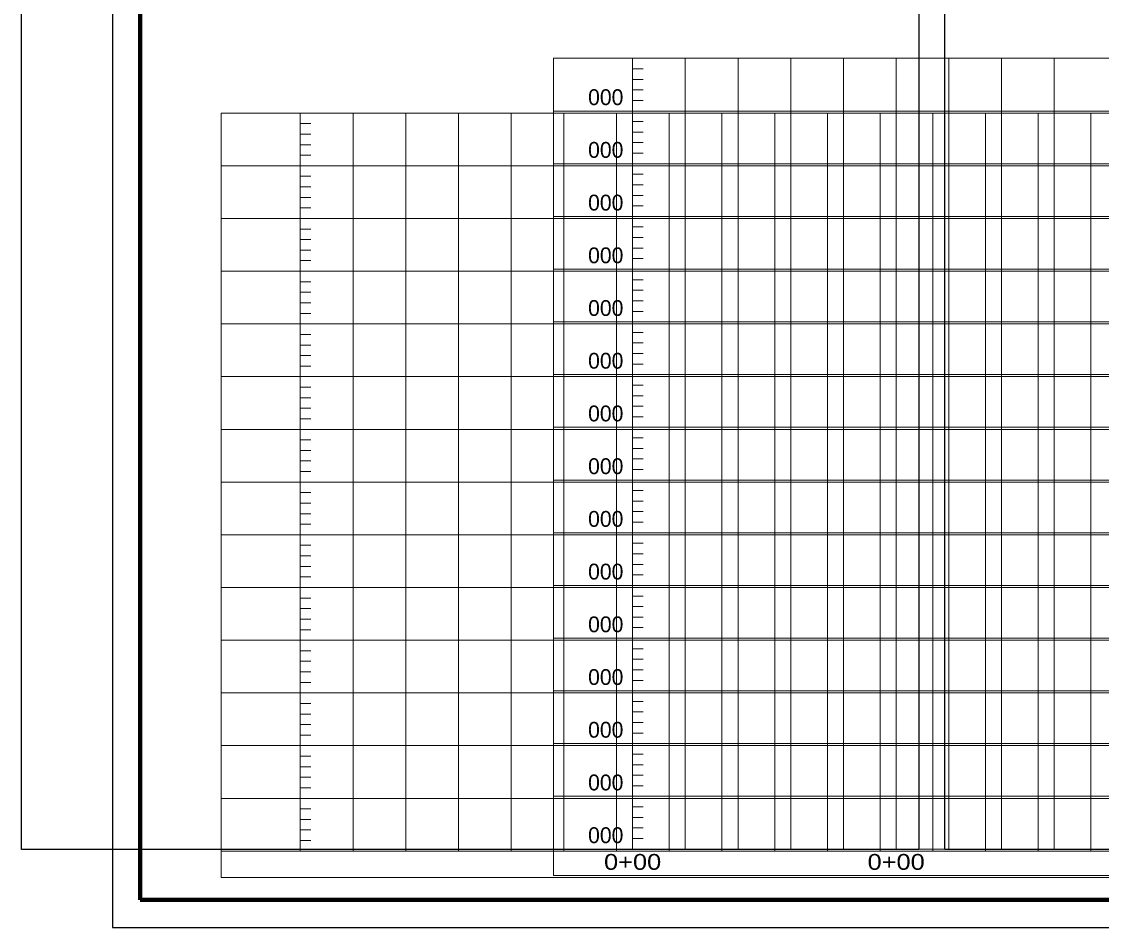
# Model space of a CAD drawing. Extents: x 2246932 to 2264252, y 7095151 to 7098651.
# Drawn here: x 2246932 to 2248981, y 7095151 to 7096869 of the extents above; entities that cross this region are included whole.
import ezdxf
from ezdxf.enums import TextEntityAlignment as Align

# ---------------------------------------------------------------- set-up
doc = ezdxf.new("R2010")
doc.units = 0
doc.header["$LTSCALE"] = 12
for name, color, linetype, lineweight in [('1', 7, 'Continuous', 80), ('59', 7, 'Continuous', 13), ('62', 7, 'Continuous', 13), ('63', 7, 'Continuous', 25)]:
    doc.layers.add(name, color=color, linetype=linetype, lineweight=lineweight)
doc.layers.add('22', color=7, linetype='Continuous')

msp = doc.modelspace()

# ---------------------------------------------------------------- linework, layer by layer
at = {"layer": '1'}
for p, q in [((2247157.08, 7098598.35), (2247157.09, 7095203.35)), ((2247157.09, 7095203.35), (2264052.09, 7095203.35))]:
    msp.add_line(p, q, dxfattribs=at)
at = {"layer": '1', "lineweight": 25}
msp.add_line((2247104.59, 7095150.85), (2264104.59, 7095150.85), dxfattribs=at)
msp.add_lwpolyline([(2264104.59, 7095150.85), (2264104.59, 7098650.85), (2247104.59, 7098650.85), (2247104.59, 7095150.85)], dxfattribs=at)
at = {"layer": '59'}
for p, q in [((2247310.97, 7096695.64), (2262610.97, 7096695.64)), ((2247310.97, 7096695.64), (2247310.97, 7095995.64)), ((2247460.97, 7095995.64), (2247460.97, 7096695.64)), ((2247560.97, 7096695.64), (2247560.97, 7095995.64)), ((2247660.97, 7095295.64), (2247660.97, 7096695.64)), ((2247760.97, 7095295.64), (2247760.97, 7096695.64)), ((2247860.97, 7095295.64), (2247860.97, 7096695.64)), ((2247960.97, 7096695.64), (2247960.97, 7095295.64)), ((2248060.97, 7095295.64), (2248060.97, 7096695.64)), ((2248160.97, 7095295.64), (2248160.97, 7096695.64)), ((2248260.97, 7095295.64), (2248260.97, 7096695.64)), ((2248360.97, 7095295.64), (2248360.97, 7096695.64)), ((2248460.97, 7096695.64), (2248460.97, 7095295.64)), ((2248560.97, 7095295.64), (2248560.97, 7096695.64)), ((2248660.97, 7095295.64), (2248660.97, 7096695.64)), ((2248760.97, 7095295.64), (2248760.97, 7096695.64)), ((2248860.97, 7095295.64), (2248860.97, 7096695.64)), ((2248960.97, 7096695.64), (2248960.97, 7095295.64)), ((2247460.97, 7096675.64), (2247480.97, 7096675.64)), ((2247460.97, 7096655.64), (2247480.97, 7096655.64)), ((2247460.97, 7096635.64), (2247480.97, 7096635.64)), ((2247460.97, 7096615.64), (2247480.97, 7096615.64)), ((2247310.97, 7096595.64), (2247460.97, 7096595.64)), ((2247460.97, 7096575.64), (2247480.97, 7096575.64)), ((2247460.97, 7096555.64), (2247480.97, 7096555.64)), ((2247460.97, 7096535.64), (2247480.97, 7096535.64)), ((2247460.97, 7096515.64), (2247480.97, 7096515.64)), ((2247310.97, 7096495.64), (2247460.97, 7096495.64)), ((2247460.97, 7096475.64), (2247480.97, 7096475.64)), ((2247460.97, 7096455.64), (2247480.97, 7096455.64)), ((2247460.97, 7096435.64), (2247480.97, 7096435.64)), ((2247460.97, 7096415.64), (2247480.97, 7096415.64)), ((2247310.97, 7096395.64), (2247460.97, 7096395.64)), ((2247460.97, 7096375.64), (2247480.97, 7096375.64)), ((2247460.97, 7096355.64), (2247480.97, 7096355.64)), ((2247460.97, 7096335.64), (2247480.97, 7096335.64)), ((2247460.97, 7096315.64), (2247480.97, 7096315.64)), ((2247310.97, 7096295.64), (2247460.97, 7096295.64)), ((2247460.97, 7096275.64), (2247480.97, 7096275.64)), ((2247460.97, 7096255.64), (2247480.97, 7096255.64)), ((2247460.97, 7096235.64), (2247480.97, 7096235.64)), ((2247460.97, 7096215.64), (2247480.97, 7096215.64)), ((2247310.97, 7096195.64), (2247460.97, 7096195.64)), ((2247460.97, 7096175.64), (2247480.97, 7096175.64)), ((2247460.97, 7096155.64), (2247480.97, 7096155.64)), ((2247460.97, 7096135.64), (2247480.97, 7096135.64)), ((2247460.97, 7096115.64), (2247480.97, 7096115.64)), ((2247310.97, 7096095.64), (2247460.97, 7096095.64)), ((2247460.97, 7096075.64), (2247480.97, 7096075.64)), ((2247460.97, 7096055.64), (2247480.97, 7096055.64)), ((2247460.97, 7096035.64), (2247480.97, 7096035.64)), ((2247460.97, 7096015.64), (2247480.97, 7096015.64)), ((2247310.97, 7095995.64), (2247310.97, 7095245.64)), ((2247310.97, 7095995.64), (2247460.97, 7095995.64)), ((2247460.97, 7095295.64), (2247460.97, 7095995.64)), ((2247560.97, 7095995.64), (2247560.97, 7095295.64)), ((2247460.97, 7095975.64), (2247480.97, 7095975.64)), ((2247460.97, 7095955.64), (2247480.97, 7095955.64)), ((2247460.97, 7095935.64), (2247480.97, 7095935.64)), ((2247460.97, 7095915.64), (2247480.97, 7095915.64)), ((2247310.97, 7095895.64), (2247460.97, 7095895.64)), ((2247460.97, 7095875.64), (2247480.97, 7095875.64)), ((2247460.97, 7095855.64), (2247480.97, 7095855.64)), ((2247460.97, 7095835.64), (2247480.97, 7095835.64)), ((2247460.97, 7095815.64), (2247480.97, 7095815.64)), ((2247310.97, 7095795.64), (2247460.97, 7095795.64)), ((2247460.97, 7095775.64), (2247480.97, 7095775.64)), ((2247460.97, 7095755.64), (2247480.97, 7095755.64)), ((2247460.97, 7095735.64), (2247480.97, 7095735.64)), ((2247460.97, 7095715.64), (2247480.97, 7095715.64)), ((2247310.97, 7095695.64), (2247460.97, 7095695.64)), ((2247460.97, 7095675.64), (2247480.97, 7095675.64)), ((2247460.97, 7095655.64), (2247480.97, 7095655.64)), ((2247460.97, 7095635.64), (2247480.97, 7095635.64)), ((2247460.97, 7095615.64), (2247480.97, 7095615.64)), ((2247310.97, 7095595.64), (2247460.97, 7095595.64)), ((2247460.97, 7095575.64), (2247480.97, 7095575.64)), ((2247460.97, 7095555.64), (2247480.97, 7095555.64)), ((2247460.97, 7095535.64), (2247480.97, 7095535.64)), ((2247460.97, 7095515.64), (2247480.97, 7095515.64)), ((2247310.97, 7095495.64), (2247460.97, 7095495.64)), ((2247460.97, 7095475.64), (2247480.97, 7095475.64)), ((2247460.97, 7095455.64), (2247480.97, 7095455.64)), ((2247460.97, 7095435.64), (2247480.97, 7095435.64)), ((2247460.97, 7095415.64), (2247480.97, 7095415.64)), ((2247310.97, 7095395.64), (2247460.97, 7095395.64)), ((2247460.97, 7095375.64), (2247480.97, 7095375.64)), ((2247460.97, 7095355.64), (2247480.97, 7095355.64)), ((2247460.97, 7095335.64), (2247480.97, 7095335.64)), ((2247460.97, 7095315.64), (2247480.97, 7095315.64)), ((2262610.97, 7095295.64), (2247310.97, 7095295.64)), ((2262610.97, 7095245.64), (2247310.97, 7095245.64))]:
    msp.add_line(p, q, dxfattribs=at)
for points in [[(2247460.97, 7096595.64), (2262460.97, 7096595.64), (2262610.97, 7096595.64)], [(2247460.97, 7096495.64), (2262460.97, 7096495.64), (2262610.97, 7096495.64)], [(2247460.97, 7096395.64), (2262460.97, 7096395.64), (2262610.97, 7096395.64)], [(2247460.97, 7096295.64), (2262460.97, 7096295.64), (2262610.97, 7096295.64)], [(2247460.97, 7096195.64), (2262460.97, 7096195.64), (2262610.97, 7096195.64)], [(2247454.92, 7096095.64), (2262460.97, 7096095.64), (2262610.97, 7096095.64)], [(2247460.97, 7095995.64), (2262460.97, 7095995.64), (2262610.97, 7095995.64)], [(2247460.97, 7095895.64), (2262460.97, 7095895.64), (2262610.97, 7095895.64)], [(2247460.97, 7095795.64), (2262460.97, 7095795.64), (2262610.97, 7095795.64)], [(2247460.97, 7095695.64), (2262460.97, 7095695.64), (2262610.97, 7095695.64)], [(2247460.97, 7095595.64), (2262460.97, 7095595.64), (2262610.97, 7095595.64)], [(2247460.97, 7095495.64), (2262460.97, 7095495.64), (2262610.97, 7095495.64)], [(2247460.97, 7095395.64), (2262460.97, 7095395.64), (2262610.97, 7095395.64)]]:
    msp.add_lwpolyline(points, dxfattribs=at)
at = {"layer": '62'}
for p, q in [((2247941.45, 7096799.51), (2247941.45, 7095249.51)), ((2247941.45, 7096799.51), (2263241.45, 7096799.51)), ((2248091.45, 7095299.51), (2248091.45, 7096799.51)), ((2248191.45, 7096799.51), (2248191.45, 7095299.51)), ((2248291.45, 7096799.51), (2248291.45, 7095299.51)), ((2248391.45, 7096799.51), (2248391.45, 7095299.51)), ((2248491.45, 7096799.51), (2248491.45, 7095299.51)), ((2248591.45, 7096799.51), (2248591.45, 7095299.51)), ((2248691.45, 7096799.51), (2248691.45, 7095299.51)), ((2248791.45, 7096799.51), (2248791.45, 7095299.51)), ((2248891.45, 7096799.51), (2248891.45, 7095299.51)), ((2248091.45, 7096779.51), (2248111.45, 7096779.51)), ((2248091.45, 7096759.51), (2248111.45, 7096759.51)), ((2248091.45, 7096739.51), (2248111.45, 7096739.51)), ((2248091.45, 7096719.51), (2248111.45, 7096719.51)), ((2247941.45, 7096699.51), (2248091.45, 7096699.51)), ((2248091.45, 7096679.51), (2248111.45, 7096679.51)), ((2248091.45, 7096659.51), (2248111.45, 7096659.51)), ((2248091.45, 7096639.51), (2248111.45, 7096639.51)), ((2248091.45, 7096619.51), (2248111.45, 7096619.51)), ((2247941.45, 7096599.51), (2248091.45, 7096599.51)), ((2248091.45, 7096579.51), (2248111.45, 7096579.51)), ((2248091.45, 7096559.51), (2248111.45, 7096559.51)), ((2248091.45, 7096539.51), (2248111.45, 7096539.51)), ((2248091.45, 7096519.51), (2248111.45, 7096519.51)), ((2247941.45, 7096499.51), (2248091.45, 7096499.51)), ((2248091.45, 7096479.51), (2248111.45, 7096479.51)), ((2248091.45, 7096459.51), (2248111.45, 7096459.51)), ((2248091.45, 7096439.51), (2248111.45, 7096439.51)), ((2248091.45, 7096419.51), (2248111.45, 7096419.51)), ((2247941.45, 7096399.51), (2248091.45, 7096399.51)), ((2248091.45, 7096379.51), (2248111.45, 7096379.51)), ((2248091.45, 7096359.51), (2248111.45, 7096359.51)), ((2248091.45, 7096339.51), (2248111.45, 7096339.51)), ((2248091.45, 7096319.51), (2248111.45, 7096319.51)), ((2247941.45, 7096299.51), (2248091.45, 7096299.51)), ((2248091.45, 7096279.51), (2248111.45, 7096279.51)), ((2248091.45, 7096259.51), (2248111.45, 7096259.51)), ((2248091.45, 7096239.51), (2248111.45, 7096239.51)), ((2248091.45, 7096219.51), (2248111.45, 7096219.51)), ((2247941.45, 7096199.51), (2248091.45, 7096199.51)), ((2248091.45, 7096179.51), (2248111.45, 7096179.51)), ((2248091.45, 7096159.51), (2248111.45, 7096159.51)), ((2248091.45, 7096139.51), (2248111.45, 7096139.51)), ((2248091.45, 7096119.51), (2248111.45, 7096119.51)), ((2247941.45, 7096099.51), (2248091.45, 7096099.51)), ((2248091.45, 7096079.51), (2248111.45, 7096079.51)), ((2248091.45, 7096059.51), (2248111.45, 7096059.51)), ((2248091.45, 7096039.51), (2248111.45, 7096039.51)), ((2248091.45, 7096019.51), (2248111.45, 7096019.51)), ((2247941.45, 7095999.51), (2248091.45, 7095999.51)), ((2248091.45, 7095979.51), (2248111.45, 7095979.51)), ((2248091.45, 7095959.51), (2248111.45, 7095959.51)), ((2248091.45, 7095939.51), (2248111.45, 7095939.51)), ((2248091.45, 7095919.51), (2248111.45, 7095919.51)), ((2247941.45, 7095899.51), (2248091.45, 7095899.51)), ((2248091.45, 7095879.51), (2248111.45, 7095879.51)), ((2248091.45, 7095859.51), (2248111.45, 7095859.51)), ((2248091.45, 7095839.51), (2248111.45, 7095839.51)), ((2248091.45, 7095819.51), (2248111.45, 7095819.51)), ((2247941.45, 7095799.51), (2248091.45, 7095799.51)), ((2248091.45, 7095779.51), (2248111.45, 7095779.51)), ((2248091.45, 7095759.51), (2248111.45, 7095759.51)), ((2248091.45, 7095739.51), (2248111.45, 7095739.51)), ((2248091.45, 7095719.51), (2248111.45, 7095719.51)), ((2247941.45, 7095699.51), (2248091.45, 7095699.51)), ((2248091.45, 7095679.51), (2248111.45, 7095679.51)), ((2248091.45, 7095659.51), (2248111.45, 7095659.51)), ((2248091.45, 7095639.51), (2248111.45, 7095639.51)), ((2248091.45, 7095619.51), (2248111.45, 7095619.51)), ((2247941.45, 7095599.51), (2248091.45, 7095599.51)), ((2248091.45, 7095579.51), (2248111.45, 7095579.51)), ((2248091.45, 7095559.51), (2248111.45, 7095559.51)), ((2248091.45, 7095539.51), (2248111.45, 7095539.51)), ((2248091.45, 7095519.51), (2248111.45, 7095519.51)), ((2247941.45, 7095499.51), (2248091.45, 7095499.51)), ((2248091.45, 7095479.51), (2248111.45, 7095479.51)), ((2248091.45, 7095459.51), (2248111.45, 7095459.51)), ((2248091.45, 7095439.51), (2248111.45, 7095439.51)), ((2248091.45, 7095419.51), (2248111.45, 7095419.51)), ((2247941.45, 7095399.51), (2248091.45, 7095399.51)), ((2248091.45, 7095379.51), (2248111.45, 7095379.51)), ((2248091.45, 7095359.51), (2248111.45, 7095359.51)), ((2248091.45, 7095339.51), (2248111.45, 7095339.51)), ((2248091.45, 7095319.51), (2248111.45, 7095319.51)), ((2263241.45, 7095299.51), (2247941.45, 7095299.51)), ((2263241.45, 7095249.51), (2247941.45, 7095249.51))]:
    msp.add_line(p, q, dxfattribs=at)
for points in [[(2248091.45, 7096699.51), (2263091.45, 7096699.51), (2263241.45, 7096699.51)], [(2248091.45, 7096599.51), (2263091.45, 7096599.51), (2263241.45, 7096599.51)], [(2248091.45, 7096499.51), (2263091.45, 7096499.51), (2263241.45, 7096499.51)], [(2248091.45, 7096399.51), (2263091.45, 7096399.51), (2263241.45, 7096399.51)], [(2248091.45, 7096299.51), (2263091.45, 7096299.51), (2263241.45, 7096299.51)], [(2248091.45, 7096199.51), (2263091.45, 7096199.51), (2263241.45, 7096199.51)], [(2248091.45, 7096099.51), (2263091.45, 7096099.51), (2263241.45, 7096099.51)], [(2248091.45, 7095999.51), (2263091.45, 7095999.51), (2263241.45, 7095999.51)], [(2248091.45, 7095899.51), (2263091.45, 7095899.51), (2263241.45, 7095899.51)], [(2248091.45, 7095799.51), (2263091.45, 7095799.51), (2263241.45, 7095799.51)], [(2248091.45, 7095699.51), (2263091.45, 7095699.51), (2263241.45, 7095699.51)], [(2248091.45, 7095599.51), (2263091.45, 7095599.51), (2263241.45, 7095599.51)], [(2248091.45, 7095499.51), (2263091.45, 7095499.51), (2263241.45, 7095499.51)], [(2248091.45, 7095399.51), (2263091.45, 7095399.51), (2263241.45, 7095399.51)]]:
    msp.add_lwpolyline(points, dxfattribs=at)
at = {"layer": '63'}
for points in [[(2248634.3, 7095298.54), (2246932.14, 7095298.54), (2246932.14, 7098498.04), (2248634.3, 7098498.04)], [(2250385.73, 7095298.54), (2248683.57, 7095298.54), (2248683.57, 7098498.04), (2250385.73, 7098498.04)]]:
    msp.add_lwpolyline(points, close=True, dxfattribs=at)

# ---------------------------------------------------------------- texts
at = {"layer": '22'}
for p in [(2248006.99, 7096710.78), (2248006.99, 7096610.78), (2248006.99, 7096510.78), (2248006.99, 7096410.78), (2248006.99, 7096310.78), (2248006.99, 7096210.78), (2248006.99, 7096110.78), (2248006.99, 7096010.78), (2248006.99, 7095910.78), (2248006.99, 7095810.78), (2248006.99, 7095710.78), (2248006.99, 7095610.78), (2248006.99, 7095510.78), (2248006.99, 7095410.78), (2248006.99, 7095310.78)]:
    msp.add_text('000', height=30, dxfattribs=at).set_placement(p)
at = {"layer": '22', "width": 1.2}
for p in [(2248091.45, 7095260.11), (2248591.45, 7095260.11)]:
    msp.add_text('0+00', height=30, dxfattribs=at).set_placement(p, align=Align.CENTER)

doc.saveas('drawing.dxf')
